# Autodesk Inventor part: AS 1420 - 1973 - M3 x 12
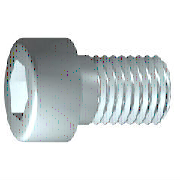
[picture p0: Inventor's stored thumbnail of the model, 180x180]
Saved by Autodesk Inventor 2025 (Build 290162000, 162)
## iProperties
Created: 2024-01
Part Number: AS 1420 - 1973 - M3 x 12
Material: Acciaio, Dolce
Description: Viti con esagono incassato metriche ISO
Document SubType Name: Modeling
Standard: AS 1420 - 1973
Designer: R5800u
Standards Organization: AS
Language: it-IT
Size Designation: M3 x 12
Categories: <MemberInstance><Categories><Category DisplayName="Elementi di fissaggio" InternalName="e4da775c-781d-43d5-af7c-5136215cf5a6" Mnemonic="FSTN"><Category DisplayN
Density: 7.85 g/cm^3
Appearance: Semilucidato
IsCustomPart: 0
Author: R5800u
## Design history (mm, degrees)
workplane "Work Plane1"
fillet "Fillet2" dims "d30" = 0.1 (= R)
revolve "Corpo" stored, may be unused: angle "d10" = 90 deg
sketch "Schizzo2"
  geometry: L1 (0, -3.85)-(0, 3.85) reference; L2 (-3.85, 0)-(3.85, 0) reference; L3 (1.443, 0)-(0.722, -1.25); L4 (0.722, -1.25)-(-0.722, -1.25); L5 (-0.722, -1.25)-(-1.443, 0); L6 (-1.443, 0)-(-0.722, 1.25); L7 (-0.722, 1.25)-(0.722, 1.25); L8 (0.722, 1.25)-(1.443, 0); 2 further points
  constraints: 12 end point, 1 coincident, 1 horizontal alignment, 1 point on line, 12 other
extrude "Intaglio" join sketch "Schizzo2" stored distance "d11" = 10; taper "d12" = 0 deg
body "Solid1"
fillet "Raccordo1" dims "d17" = 0.3 (= RR)
feature "Filettatura" dims "d13" = 10.75 (= GEL), "d14" = 0
chamfer "Smusso1" distance "d15" = 0.30673 (= -0.5 x SPD + 0.5 x GD); stored, may be unused: second distance "d16" = 0.30673 (= GUL), angle "d27" = 45 deg
sketch "Schizzo1"
  geometry: L1 (-0.867, 0)-(12, 0); L2 (12, 0)-(12, 1.5); L3 (12, 1.5)-(1.25, 1.5); L4 (1.25, 1.5)-(0.943, 1.5); L5 (0.943, 1.5)-(0, 1.5); L6 (0, 1.5)-(0, 2.75); L7 (0, 2.75)-(-3, 2.75); L8 (-3, 2.75)-(-3, 1.443); L9 (-3, 1.443)-(-1.7, 1.443); L10 (-1.7, 1.443)-(-0.867, 0); L11 (-6, 0)-(15, 0) reference; L12 (0, -0.55)-(0, 3.3) reference; L13 (1.25, 1.5)-(0, 1.5)
  constraints: 22 end point, 6 parallel, 2 collinear, 2 perpendicular, 1 horizontal, 1 point on line
  dimensions: "d1" = 10.75 distance from line of L3.end L2 (= GEL); "d2" = 0.30683 distance of L4.end L3.end (computed from GAL); "d3" = 3 distance between parallel lines of L8 L6 (= KOH); "d4" = 1.3 distance of L8.end L9.end (= INTI); "d5" = 60 deg angle of L10 L1; "d6" = 3 diameter of L3 L1 (= GD); "d7" = 3 diameter of L5 L1 (= BDM); "d8" = 2.88675 diameter of L9 L1 (= 1.1547 x SW); "d9" = 5.5 diameter of L7 L1 (= KOD); "d26" = 12 distance between parallel lines of L12 L2 (= NLG)
other parameters: "GD" = 3 (= NND) [user parameter; used in 2 equation terms], "NLG" = 12 [user parameter; used in 1 equation term], "GEL" = 10.75 [user parameter; used in 2 equation terms], "KOD" = 5.5 [user parameter; used in 1 equation term], "KOH" = 3 (= NND) [user parameter; used in 1 equation term], "INTI" = 1.3 [user parameter; used in 1 equation term], "GAL" = 0.30673 (= 0.61345 x PTC) [user parameter; used in 1 equation term], "GUL" = 0.30673 (= 0.61345 x PTC) [user parameter; used in 1 equation term], "BDM" = 3 (= NND) [user parameter; used in 1 equation term], "SW" = 2.5 [user parameter; used in 2 equation terms], "RR" = 0.3 (= 0.1 x NND) [user parameter; used in 1 equation term], "SPD" = 2.38655 (= NND - 1.2269 x PTC) [user parameter; used in 1 equation term], "d19" = 0, "d28" = 0, "d29" = 0, "R" = 0.1 [user parameter; used in 1 equation term], "PHH" = 0.13 [user parameter], "GD1" = 2.38655 (= THREADDIA - 1.2269 x PTC) [user parameter], "THREADDIA" = 3 [user parameter; used in 1 equation term], "FAWI" = 45 deg [user parameter], "PTC" = 0.5 [user parameter; used in 5 equation terms], "KOH1" = 2.7 [user parameter], "NND" = 3 [user parameter; used in 5 equation terms], "TOA" = 30 deg [user parameter], "E0" = 2.8875 (= 1.155 x SW) [user parameter]
